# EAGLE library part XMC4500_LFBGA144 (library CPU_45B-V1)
Infineon XMC4500 144Pin LFBGA ARM Cortex M4
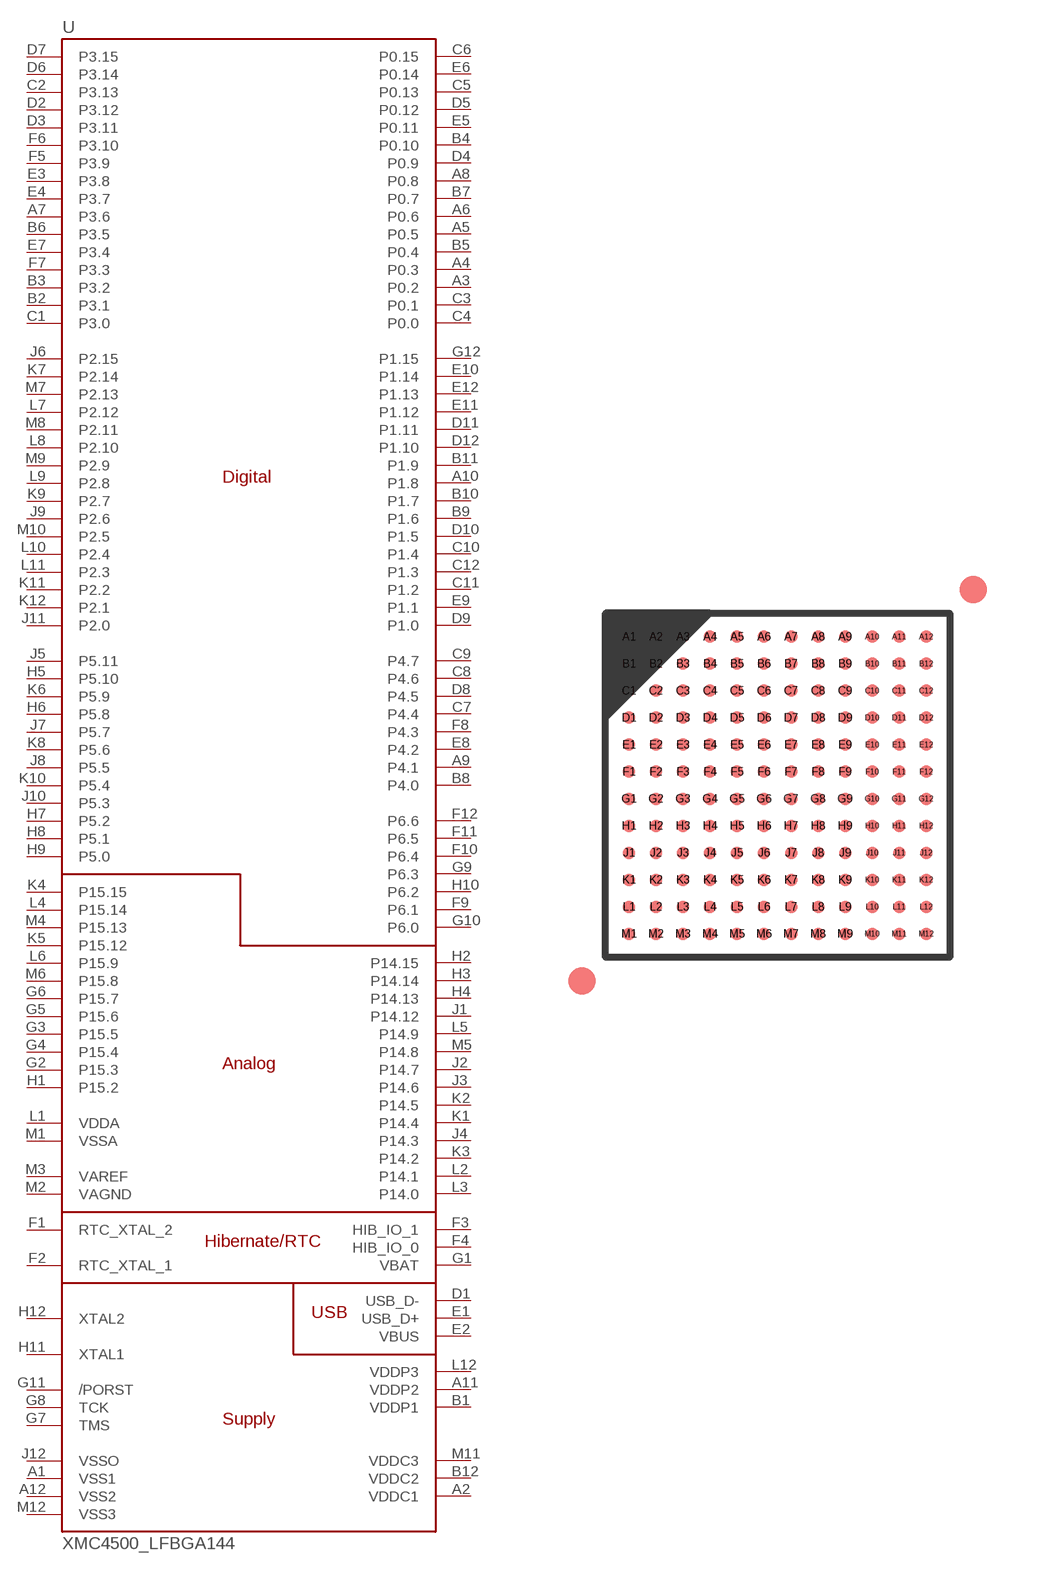
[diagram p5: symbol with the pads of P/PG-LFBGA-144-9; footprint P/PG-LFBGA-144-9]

Designator prefix U

## XMC4500_LFBGA144  [P/PG-LFBGA-144-9]
A1  VSS1
A2  VDDC1
A3  P0.2
A4  P0.3
A5  P0.5
A6  P0.6
A7  P3.6
A8  P0.8
A9  P4.1
A10  P1.8
A11  VDDP2
A12  VSS2
B1  VDDP1
B2  P3.1
B3  P3.2
B4  P0.10
B5  P0.4
B6  P3.5
B7  P0.7
B8  P4.0
B9  P1.6
B10  P1.7
B11  P1.9
B12  VDDC2
C1  P3.0
C2  P3.13
C3  P0.1
C4  P0.0
C5  P0.13
C6  P0.15
C7  P4.4
C8  P4.6
C9  P4.7
C10  P1.4
C11  P1.2
C12  P1.3
D1  USB_D-
D2  P3.12
D3  P3.11
D4  P0.9
D5  P0.12
D6  P3.14
D7  P3.15
D8  P4.5
D9  P1.0
D10  P1.5
D11  P1.11
D12  P1.10
E1  USB_D+
E2  VBUS
E3  P3.8
E4  P3.7
E5  P0.11
E6  P0.14
E7  P3.4
E8  P4.2
E9  P1.1
E10  P1.14
E11  P1.12
E12  P1.13
F1  RTC_XTAL_2
F2  RTC_XTAL_1
F3  HIB_IO_1
F4  HIB_IO_0
F5  P3.9
F6  P3.10
F7  P3.3
F8  P4.3
F9  P6.1
F10  P6.4
F11  P6.5
F12  P6.6
G1  VBAT
G2  P15.3
G3  P15.5
G4  P15.4
G5  P15.6
G6  P15.7
G7  TMS
G8  TCK
G9  P6.3
G10  P6.0
G11  /PORST
G12  P1.15
H1  P15.2
H2  P14.15
H3  P14.14
H4  P14.13
H5  P5.10
H6  P5.8
H7  P5.2
H8  P5.1
H9  P5.0
H10  P6.2
H11  XTAL1
H12  XTAL2
J1  P14.12
J2  P14.7
J3  P14.6
J4  P14.3
J5  P5.11
J6  P2.15
J7  P5.7
J8  P5.5
J9  P2.6
J10  P5.3
J11  P2.0
J12  VSSO
K1  P14.4
K2  P14.5
K3  P14.2
K4  P15.15
K5  P15.12
K6  P5.9
K7  P2.14
K8  P5.6
K9  P2.7
K10  P5.4
K11  P2.2
K12  P2.1
L1  VDDA
L2  P14.1
L3  P14.0
L4  P15.14
L5  P14.9
L6  P15.9
L7  P2.12
L8  P2.10
L9  P2.8
L10  P2.4
L11  P2.3
L12  VDDP3
M1  VSSA
M2  VAGND
M3  VAREF
M4  P15.13
M5  P14.8
M6  P15.8
M7  P2.13
M8  P2.11
M9  P2.9
M10  P2.5
M11  VDDC3
M12  VSS3

## Footprint P/PG-LFBGA-144-9 (pad centres in mm)
P/PG-LFBGA-144-9 144pins 0.8mm pitch BGA IFX Reference: P/PG-LFBGA-144-9 10mm x 10mm x 1.4mm, 0.8mm pitch
smd 0.37 x 0.37: A1 -4.4,4.4; A2 -3.6,4.4; A3 -2.8,4.4; A4 -2,4.4; A5 -1.2,4.4; A6 -0.4,4.4; A7 0.4,4.4; A8 1.2,4.4; A9 2,4.4; A10 2.8,4.4; A11 3.6,4.4; A12 4.4,4.4; B1 -4.4,3.6; B2 -3.6,3.6; B3 -2.8,3.6; B4 -2,3.6; B5 -1.2,3.6; B6 -0.4,3.6; B7 0.4,3.6; B8 1.2,3.6; B9 2,3.6; B10 2.8,3.6; B11 3.6,3.6; B12 4.4,3.6; C1 -4.4,2.8; C2 -3.6,2.8; C3 -2.8,2.8; C4 -2,2.8; C5 -1.2,2.8; C6 -0.4,2.8; C7 0.4,2.8; C8 1.2,2.8; C9 2,2.8; C10 2.8,2.8; C11 3.6,2.8; C12 4.4,2.8; D1 -4.4,2; D2 -3.6,2; D3 -2.8,2; D4 -2,2; D5 -1.2,2; D6 -0.4,2; D7 0.4,2; D8 1.2,2; D9 2,2; D10 2.8,2; D11 3.6,2; D12 4.4,2; E1 -4.4,1.2; E2 -3.6,1.2; E3 -2.8,1.2; E4 -2,1.2; E5 -1.2,1.2; E6 -0.4,1.2; E7 0.4,1.2; E8 1.2,1.2; E9 2,1.2; E10 2.8,1.2; E11 3.6,1.2; E12 4.4,1.2; F1 -4.4,0.4; F2 -3.6,0.4; F3 -2.8,0.4; F4 -2,0.4; F5 -1.2,0.4; F6 -0.4,0.4; F7 0.4,0.4; F8 1.2,0.4; F9 2,0.4; F10 2.8,0.4; F11 3.6,0.4; F12 4.4,0.4; G1 -4.4,-0.4; G2 -3.6,-0.4; G3 -2.8,-0.4; G4 -2,-0.4; G5 -1.2,-0.4; G6 -0.4,-0.4; G7 0.4,-0.4; G8 1.2,-0.4; G9 2,-0.4; G10 2.8,-0.4; G11 3.6,-0.4; G12 4.4,-0.4; H1 -4.4,-1.2; H2 -3.6,-1.2; H3 -2.8,-1.2; H4 -2,-1.2; H5 -1.2,-1.2; H6 -0.4,-1.2; H7 0.4,-1.2; H8 1.2,-1.2; H9 2,-1.2; H10 2.8,-1.2; H11 3.6,-1.2; H12 4.4,-1.2; J1 -4.4,-2; J2 -3.6,-2; J3 -2.8,-2; J4 -2,-2; J5 -1.2,-2; J6 -0.4,-2; J7 0.4,-2; J8 1.2,-2; J9 2,-2; J10 2.8,-2; J11 3.6,-2; J12 4.4,-2; K1 -4.4,-2.8; K2 -3.6,-2.8; K3 -2.8,-2.8; K4 -2,-2.8; K5 -1.2,-2.8; K6 -0.4,-2.8; K7 0.4,-2.8; K8 1.2,-2.8; K9 2,-2.8; K10 2.8,-2.8; K11 3.6,-2.8; K12 4.4,-2.8; L1 -4.4,-3.6; L2 -3.6,-3.6; L3 -2.8,-3.6; L4 -2,-3.6; L5 -1.2,-3.6; L6 -0.4,-3.6; L7 0.4,-3.6; L8 1.2,-3.6; L9 2,-3.6; L10 2.8,-3.6; L11 3.6,-3.6; L12 4.4,-3.6; M1 -4.4,-4.4; M2 -3.6,-4.4; M3 -2.8,-4.4; M4 -2,-4.4; M5 -1.2,-4.4; M6 -0.4,-4.4; M7 0.4,-4.4; M8 1.2,-4.4; M9 2,-4.4; M10 2.8,-4.4; M11 3.6,-4.4; M12 4.4,-4.4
